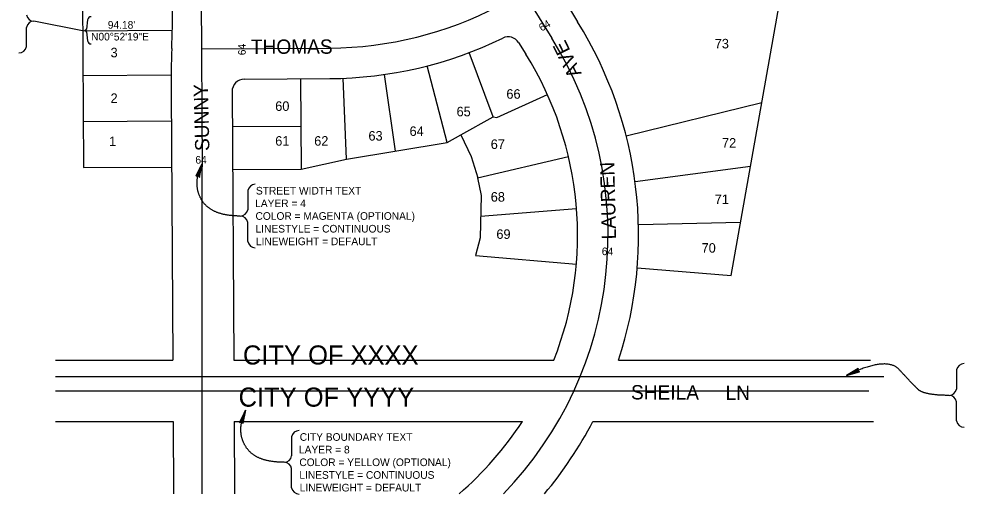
# Model space of a CAD drawing. Extents: x 6387474 to 6390971, y 1972046 to 1973920.
# Drawn here: x 6389012 to 6390004, y 1972046 to 1972544 of the extents above; entities that cross this region are included whole.
import ezdxf

# ---------------------------------------------------------------- set-up
doc = ezdxf.new("R2010")
doc.units = 0
for name, color, linetype in [('1', 7, 'Continuous'), ('2', 7, 'Continuous'), ('3', 7, 'Continuous'), ('4', 7, 'Continuous'), ('7', 7, 'Continuous'), ('8', 7, 'Continuous')]:
    doc.layers.add(name, color=color, linetype=linetype)

msp = doc.modelspace()

# ---------------------------------------------------------------- linework, layer by layer
at = {"layer": '1'}
for p, q in [((6389072.58, 1973552.73), (6389079.62, 1972388)), ((6389759.25, 1972274.95), (6389876.15, 1972929.69)), ((6389355.67, 1972396.74), (6389461.2, 1972414.36)), ((6389461.2, 1972414.36), (6389475.57, 1972422.29)), ((6389475.57, 1972422.29), (6389486.58, 1972399.76)), ((6389308.14, 1972386.48), (6389355.67, 1972396.74)), ((6389486.58, 1972399.76), (6389493.36, 1972377.14)), ((6389079.62, 1972388), (6389172.12, 1972388.56)), ((6389236.14, 1972386.04), (6389308.14, 1972386.48)), ((6389493.27, 1972377.12), (6389496.88, 1972358.76)), ((6389496.88, 1972358.76), (6389495.98, 1972314.39)), ((6389495.98, 1972314.39), (6389491.18, 1972295.81)), ((6389491.18, 1972295.81), (6389596.9, 1972286.77)), ((6389660.8, 1972282.98), (6389759.25, 1972274.95))]:
    msp.add_line(p, q, dxfattribs=at)
at = {"layer": '2'}
for p, q in [((6389202.67, 1972629.26), (6389204.12, 1972388.75)), ((6389540.91, 1972572.1), (6389571.1, 1972523.69)), ((6389203.37, 1972512.5), (6389337.91, 1972513.31)), ((6389204.12, 1972045.99), (6389204.12, 1972388.75)), ((6389050.21, 1972153.98), (6389903.78, 1972153.98))]:
    msp.add_line(p, q, dxfattribs=at)
for centre, radius, start, end in [((6389335.56, 1972901.3), 388, 270.34667, 18.92365), ((6389240.2, 1972317.28), 390, 315.92273, 31.95472)]:
    msp.add_arc(centre, radius, start, end, dxfattribs=at)
at = {"layer": '3'}
for p, q in [((6389078.76, 1972531.51), (6389172.94, 1972532.08)), ((6389509.78, 1972441.18), (6389484.28, 1972508.52)), ((6389461.2, 1972414.36), (6389440.49, 1972494.62)), ((6389079.04, 1972484.53), (6389171.69, 1972485.09)), ((6389407, 1972405.31), (6389395.46, 1972485.6)), ((6389307.56, 1972481.13), (6389308.14, 1972386.48)), ((6389355.67, 1972396.74), (6389352.05, 1972481.63)), ((6389513.51, 1972440.63), (6389566.5, 1972464.55)), ((6389791.56, 1972455.9), (6389649.3, 1972420.82)), ((6389079.33, 1972436.47), (6389171.83, 1972437.03)), ((6389475.57, 1972422.29), (6389509.78, 1972441.18)), ((6389509.78, 1972441.18), (6389513.51, 1972440.63)), ((6389235.87, 1972431.04), (6389307.86, 1972431.48)), ((6389493.27, 1972377.12), (6389588.59, 1972399.66)), ((6389779.64, 1972389.17), (6389658.5, 1972373.03)), ((6389496.44, 1972337.18), (6389597.12, 1972345)), ((6389769.17, 1972330.53), (6389662.07, 1972327.85))]:
    msp.add_line(p, q, dxfattribs=at)
at = {"layer": '4'}
for p, q in [((6389590.63, 1972552.84), (6389598.25, 1972540.63)), ((6389536.33, 1972518.97), (6389543.95, 1972506.75)), ((6389248.57, 1972480.77), (6389338.1, 1972481.31)), ((6389171.65, 1972467.3), (6389173.35, 1972185.98)), ((6389235.64, 1972467.69), (6389237.35, 1972185.98)), ((6389050.21, 1972185.98), (6389173.35, 1972185.98)), ((6389237.35, 1972185.98), (6389573.25, 1972185.98)), ((6389641.25, 1972185.98), (6389905.57, 1972185.98)), ((6389050.21, 1972121.98), (6389173.73, 1972121.98)), ((6389173.73, 1972121.98), (6389174.19, 1972045.99)), ((6389237.74, 1972121.98), (6389540.23, 1972121.98)), ((6389237.74, 1972121.98), (6389238.2, 1972045.99)), ((6389614.29, 1972121.98), (6389908.78, 1972121.98))]:
    msp.add_line(p, q, dxfattribs=at)
for centre, radius, start, end in [((6388172.12, 1972551.26), 1001, 357.80051, 0.34648), ((6389240.2, 1972317.28), 422, 341.87222, 31.95472), ((6389335.56, 1972901.3), 420, 270.34667, 295.98864), ((6389525.3, 1972512.09), 13, 31.95472, 115.98864), ((6390196.63, 1972473.51), 1025, 177.8005, 180.34667), ((6389240.2, 1972317.28), 358, 338.48409, 31.95472), ((6389248.64, 1972467.77), 13, 90.34667, 180.34667), ((6389240.2, 1972317.28), 358, 310.72876, 326.939), ((6389240.2, 1972317.28), 422, 319.99318, 332.43226)]:
    msp.add_arc(centre, radius, start, end, dxfattribs=at)
at = {"layer": '8'}
for p, q in [((6389084.02, 1972542.9), (6389082.81, 1972533.08)), ((6389019.82, 1972514.85), (6389019.82, 1972534.83)), ((6389078.76, 1972531.51), (6389027.71, 1972541.49)), ((6389082.81, 1972530.18), (6389084.02, 1972520.77)), ((6389203.73, 1972391.72), (6389197.52, 1972379.01)), ((6389201.33, 1972377.78), (6389203.73, 1972391.72)), ((6389252.13, 1972363.86), (6389252.13, 1972343.88)), ((6389252.13, 1972310.57), (6389252.13, 1972330.55)), ((6389892.6, 1972177.45), (6389880.46, 1972170.21)), ((6389995.91, 1972175.87), (6389995.91, 1972155.89)), ((6389050.21, 1972169.01), (6389919.45, 1972169.01)), ((6389880.46, 1972170.21), (6389894.15, 1972173.76)), ((6389995.91, 1972122.59), (6389995.91, 1972142.57)), ((6389249.7, 1972133.57), (6389243.49, 1972120.87)), ((6389247.3, 1972119.64), (6389249.7, 1972133.57)), ((6389298.1, 1972105.72), (6389298.1, 1972085.74)), ((6389298.1, 1972052.43), (6389298.1, 1972072.41))]:
    msp.add_line(p, q, dxfattribs=at)
for points in [[(6389197.52, 1972379.01), (6389198.03, 1972379.29), (6389203.73, 1972391.72)], [(6389198.03, 1972379.29), (6389198.59, 1972379.44), (6389203.73, 1972391.72)], [(6389198.59, 1972379.44), (6389199.16, 1972379.46), (6389203.73, 1972391.72)], [(6389199.16, 1972379.46), (6389199.73, 1972379.35), (6389203.73, 1972391.72)], [(6389199.73, 1972379.35), (6389200.26, 1972379.11), (6389203.73, 1972391.72)], [(6389203.73, 1972391.72), (6389200.26, 1972379.11), (6389200.71, 1972378.75)], [(6389203.73, 1972391.72), (6389200.71, 1972378.75), (6389201.08, 1972378.3)], [(6389203.73, 1972391.72), (6389201.08, 1972378.3), (6389201.33, 1972377.78)], [(6389880.46, 1972170.21), (6389892.37, 1972176.92), (6389892.6, 1972177.45)], [(6389880.46, 1972170.21), (6389892.27, 1972176.35), (6389892.37, 1972176.92)], [(6389880.46, 1972170.21), (6389892.29, 1972175.77), (6389892.27, 1972176.35)], [(6389892.45, 1972175.22), (6389892.29, 1972175.77), (6389880.46, 1972170.21)], [(6389892.74, 1972174.71), (6389892.45, 1972175.22), (6389880.46, 1972170.21)], [(6389893.13, 1972174.29), (6389892.74, 1972174.71), (6389880.46, 1972170.21)], [(6389893.61, 1972173.96), (6389893.13, 1972174.29), (6389880.46, 1972170.21)], [(6389894.15, 1972173.76), (6389893.61, 1972173.96), (6389880.46, 1972170.21)], [(6389243.49, 1972120.87), (6389244, 1972121.14), (6389249.7, 1972133.57)], [(6389244, 1972121.14), (6389244.55, 1972121.3), (6389249.7, 1972133.57)], [(6389244.55, 1972121.3), (6389245.13, 1972121.32), (6389249.7, 1972133.57)], [(6389245.13, 1972121.32), (6389245.7, 1972121.2), (6389249.7, 1972133.57)], [(6389245.7, 1972121.2), (6389246.23, 1972120.96), (6389249.7, 1972133.57)], [(6389249.7, 1972133.57), (6389246.23, 1972120.96), (6389246.68, 1972120.61)], [(6389249.7, 1972133.57), (6389246.68, 1972120.61), (6389247.04, 1972120.16)], [(6389249.7, 1972133.57), (6389247.04, 1972120.16), (6389247.3, 1972119.64)]]:
    msp.add_lwpolyline(points, close=True, dxfattribs=at)
for points in [[(6389198.97, 1972373.96), (6389199.02, 1972374.58), (6389199.08, 1972375.2), (6389199.14, 1972375.83), (6389199.22, 1972376.46), (6389199.31, 1972377.09), (6389199.4, 1972377.72), (6389199.51, 1972378.36), (6389199.62, 1972379), (6389199.75, 1972379.64), (6389199.89, 1972380.29), (6389200.03, 1972380.93), (6389200.19, 1972381.59), (6389200.36, 1972382.24), (6389200.53, 1972382.9), (6389200.72, 1972383.56), (6389200.91, 1972384.22), (6389201.12, 1972384.89), (6389201.34, 1972385.56), (6389201.56, 1972386.23), (6389201.8, 1972386.91), (6389202.04, 1972387.58), (6389202.3, 1972388.27), (6389202.57, 1972388.95), (6389202.84, 1972389.64), (6389203.13, 1972390.33), (6389203.43, 1972391.02), (6389203.73, 1972391.72)], [(6389244.24, 1972337.22), (6389243.31, 1972337.22), (6389242.38, 1972337.23), (6389241.47, 1972337.25), (6389240.56, 1972337.28), (6389239.67, 1972337.32), (6389238.78, 1972337.36), (6389237.9, 1972337.41), (6389237.03, 1972337.47), (6389236.18, 1972337.54), (6389235.33, 1972337.62), (6389234.49, 1972337.7), (6389233.66, 1972337.79), (6389232.84, 1972337.89), (6389232.04, 1972338), (6389231.24, 1972338.12), (6389230.45, 1972338.24), (6389229.67, 1972338.38), (6389228.9, 1972338.52), (6389228.14, 1972338.67), (6389227.39, 1972338.82), (6389226.64, 1972338.99), (6389225.91, 1972339.16), (6389225.19, 1972339.34), (6389224.48, 1972339.53), (6389223.78, 1972339.72), (6389223.09, 1972339.93), (6389222.4, 1972340.14), (6389221.73, 1972340.36), (6389221.07, 1972340.59), (6389220.41, 1972340.83), (6389219.77, 1972341.07), (6389219.13, 1972341.33), (6389218.51, 1972341.59), (6389217.9, 1972341.85), (6389217.29, 1972342.13), (6389216.69, 1972342.42), (6389216.11, 1972342.71), (6389215.53, 1972343.01), (6389214.97, 1972343.32), (6389214.41, 1972343.64), (6389213.86, 1972343.96), (6389213.33, 1972344.29), (6389212.8, 1972344.63), (6389212.28, 1972344.98), (6389211.77, 1972345.34), (6389211.28, 1972345.71), (6389210.79, 1972346.08), (6389210.31, 1972346.46), (6389209.84, 1972346.85), (6389209.38, 1972347.25), (6389208.93, 1972347.65), (6389208.49, 1972348.07), (6389208.06, 1972348.49), (6389207.64, 1972348.92), (6389207.23, 1972349.35), (6389206.83, 1972349.8), (6389206.43, 1972350.25), (6389206.05, 1972350.71), (6389205.68, 1972351.18), (6389205.32, 1972351.66), (6389204.97, 1972352.15), (6389204.62, 1972352.64), (6389204.29, 1972353.14), (6389203.97, 1972353.65), (6389203.65, 1972354.16), (6389203.35, 1972354.68), (6389203.06, 1972355.2), (6389202.77, 1972355.72), (6389202.5, 1972356.24), (6389202.23, 1972356.77), (6389201.98, 1972357.3), (6389201.74, 1972357.83), (6389201.5, 1972358.37), (6389201.28, 1972358.91), (6389201.07, 1972359.45), (6389200.86, 1972359.99), (6389200.67, 1972360.54), (6389200.49, 1972361.09), (6389200.31, 1972361.65), (6389200.15, 1972362.2), (6389199.99, 1972362.76), (6389199.85, 1972363.33), (6389199.72, 1972363.89), (6389199.59, 1972364.46), (6389199.48, 1972365.03), (6389199.38, 1972365.61), (6389199.28, 1972366.18), (6389199.2, 1972366.77), (6389199.13, 1972367.35), (6389199.06, 1972367.94), (6389199.01, 1972368.52), (6389198.96, 1972369.12), (6389198.93, 1972369.71), (6389198.91, 1972370.31), (6389198.89, 1972370.91), (6389198.89, 1972371.52), (6389198.9, 1972372.12), (6389198.91, 1972372.73), (6389198.94, 1972373.35), (6389198.97, 1972373.96)], [(6389938.55, 1972173.17), (6389938.08, 1972173.68), (6389937.61, 1972174.19), (6389937.13, 1972174.7), (6389936.65, 1972175.22), (6389936.16, 1972175.75), (6389935.67, 1972176.28), (6389935.16, 1972176.81), (6389934.63, 1972177.31), (6389934.09, 1972177.78), (6389933.52, 1972178.23), (6389932.93, 1972178.65), (6389932.32, 1972179.05), (6389931.69, 1972179.43), (6389931.05, 1972179.78), (6389930.37, 1972180.11), (6389929.68, 1972180.41), (6389928.97, 1972180.69), (6389928.24, 1972180.94), (6389927.49, 1972181.17), (6389926.71, 1972181.37), (6389925.92, 1972181.55), (6389925.1, 1972181.71), (6389924.27, 1972181.84), (6389923.41, 1972181.95), (6389922.54, 1972182.03), (6389921.64, 1972182.08), (6389920.72, 1972182.12), (6389919.78, 1972182.12), (6389918.82, 1972182.11), (6389917.84, 1972182.07), (6389916.84, 1972182), (6389915.82, 1972181.91), (6389914.78, 1972181.8), (6389913.72, 1972181.66), (6389912.63, 1972181.49), (6389911.53, 1972181.31), (6389910.41, 1972181.09), (6389909.26, 1972180.86), (6389908.1, 1972180.59), (6389906.91, 1972180.31), (6389905.7, 1972180), (6389904.48, 1972179.66), (6389903.23, 1972179.3), (6389901.96, 1972178.92), (6389900.67, 1972178.51), (6389899.36, 1972178.08), (6389898.03, 1972177.62), (6389896.68, 1972177.14), (6389895.31, 1972176.63), (6389893.92, 1972176.1), (6389892.5, 1972175.54), (6389891.07, 1972174.96), (6389889.61, 1972174.36), (6389888.14, 1972173.73), (6389886.64, 1972173.07), (6389885.13, 1972172.39), (6389883.59, 1972171.69), (6389882.03, 1972170.96), (6389880.46, 1972170.21)], [(6389988.02, 1972149.23), (6389987.05, 1972149.23), (6389986.08, 1972149.24), (6389985.13, 1972149.25), (6389984.19, 1972149.27), (6389983.27, 1972149.29), (6389982.36, 1972149.31), (6389981.47, 1972149.34), (6389980.59, 1972149.38), (6389979.72, 1972149.42), (6389978.87, 1972149.46), (6389978.03, 1972149.51), (6389977.2, 1972149.56), (6389976.39, 1972149.62), (6389975.59, 1972149.68), (6389974.81, 1972149.75), (6389974.04, 1972149.82), (6389973.28, 1972149.89), (6389972.54, 1972149.97), (6389971.81, 1972150.06), (6389971.1, 1972150.15), (6389970.4, 1972150.24), (6389969.71, 1972150.34), (6389969.04, 1972150.44), (6389968.38, 1972150.55), (6389967.74, 1972150.66), (6389967.11, 1972150.78), (6389966.49, 1972150.9), (6389965.89, 1972151.03), (6389965.3, 1972151.16), (6389964.72, 1972151.29), (6389964.16, 1972151.43), (6389963.62, 1972151.58), (6389963.08, 1972151.72), (6389962.56, 1972151.88), (6389962.06, 1972152.04), (6389961.57, 1972152.2), (6389961.09, 1972152.37), (6389960.63, 1972152.54), (6389960.18, 1972152.71), (6389959.74, 1972152.9), (6389959.32, 1972153.08), (6389958.91, 1972153.27), (6389958.52, 1972153.47), (6389958.14, 1972153.67), (6389957.77, 1972153.87), (6389957.42, 1972154.08), (6389957.08, 1972154.29), (6389956.76, 1972154.51), (6389956.45, 1972154.73), (6389956.15, 1972154.96), (6389955.87, 1972155.19), (6389955.6, 1972155.42), (6389955.35, 1972155.67), (6389955.1, 1972155.91), (6389954.84, 1972156.16), (6389954.58, 1972156.42), (6389954.32, 1972156.68), (6389954.05, 1972156.95), (6389953.78, 1972157.22), (6389953.5, 1972157.5), (6389953.22, 1972157.78), (6389952.93, 1972158.07), (6389952.64, 1972158.37), (6389952.34, 1972158.67), (6389952.04, 1972158.98), (6389951.73, 1972159.29), (6389951.42, 1972159.61), (6389951.11, 1972159.93), (6389950.79, 1972160.26), (6389950.46, 1972160.59), (6389950.14, 1972160.93), (6389949.8, 1972161.28), (6389949.46, 1972161.63), (6389949.12, 1972161.98), (6389948.77, 1972162.34), (6389948.42, 1972162.71), (6389948.06, 1972163.08), (6389947.7, 1972163.46), (6389947.33, 1972163.84), (6389946.96, 1972164.23), (6389946.59, 1972164.63), (6389946.2, 1972165.03), (6389945.82, 1972165.43), (6389945.43, 1972165.84), (6389945.03, 1972166.26), (6389944.63, 1972166.68), (6389944.23, 1972167.11), (6389943.82, 1972167.54), (6389943.41, 1972167.98), (6389942.99, 1972168.43), (6389942.57, 1972168.88), (6389942.14, 1972169.33), (6389941.71, 1972169.79), (6389941.27, 1972170.26), (6389940.83, 1972170.73), (6389940.38, 1972171.21), (6389939.93, 1972171.69), (6389939.48, 1972172.18), (6389939.02, 1972172.67), (6389938.55, 1972173.17)], [(6389244.94, 1972115.82), (6389244.99, 1972116.44), (6389245.05, 1972117.06), (6389245.11, 1972117.69), (6389245.19, 1972118.31), (6389245.27, 1972118.95), (6389245.37, 1972119.58), (6389245.48, 1972120.22), (6389245.59, 1972120.86), (6389245.72, 1972121.5), (6389245.86, 1972122.14), (6389246, 1972122.79), (6389246.16, 1972123.44), (6389246.32, 1972124.1), (6389246.5, 1972124.76), (6389246.69, 1972125.42), (6389246.88, 1972126.08), (6389247.09, 1972126.75), (6389247.3, 1972127.42), (6389247.53, 1972128.09), (6389247.77, 1972128.76), (6389248.01, 1972129.44), (6389248.27, 1972130.12), (6389248.54, 1972130.81), (6389248.81, 1972131.49), (6389249.1, 1972132.18), (6389249.39, 1972132.88), (6389249.7, 1972133.57)], [(6389290.21, 1972079.08), (6389289.28, 1972079.08), (6389288.35, 1972079.09), (6389287.44, 1972079.11), (6389286.53, 1972079.14), (6389285.63, 1972079.18), (6389284.75, 1972079.22), (6389283.87, 1972079.27), (6389283, 1972079.33), (6389282.15, 1972079.4), (6389281.3, 1972079.48), (6389280.46, 1972079.56), (6389279.63, 1972079.65), (6389278.81, 1972079.75), (6389278, 1972079.86), (6389277.2, 1972079.98), (6389276.42, 1972080.1), (6389275.64, 1972080.23), (6389274.87, 1972080.37), (6389274.11, 1972080.52), (6389273.35, 1972080.68), (6389272.61, 1972080.84), (6389271.88, 1972081.02), (6389271.16, 1972081.2), (6389270.45, 1972081.39), (6389269.75, 1972081.58), (6389269.05, 1972081.79), (6389268.37, 1972082), (6389267.7, 1972082.22), (6389267.03, 1972082.45), (6389266.38, 1972082.69), (6389265.74, 1972082.93), (6389265.1, 1972083.18), (6389264.48, 1972083.44), (6389263.86, 1972083.71), (6389263.26, 1972083.99), (6389262.66, 1972084.27), (6389262.08, 1972084.57), (6389261.5, 1972084.87), (6389260.94, 1972085.18), (6389260.38, 1972085.49), (6389259.83, 1972085.82), (6389259.3, 1972086.15), (6389258.77, 1972086.49), (6389258.25, 1972086.84), (6389257.74, 1972087.2), (6389257.24, 1972087.56), (6389256.76, 1972087.94), (6389256.28, 1972088.32), (6389255.81, 1972088.71), (6389255.35, 1972089.1), (6389254.9, 1972089.51), (6389254.46, 1972089.92), (6389254.03, 1972090.34), (6389253.61, 1972090.77), (6389253.2, 1972091.21), (6389252.79, 1972091.66), (6389252.4, 1972092.11), (6389252.02, 1972092.57), (6389251.65, 1972093.04), (6389251.29, 1972093.52), (6389250.93, 1972094), (6389250.59, 1972094.5), (6389250.26, 1972095), (6389249.93, 1972095.51), (6389249.62, 1972096.02), (6389249.32, 1972096.54), (6389249.02, 1972097.05), (6389248.74, 1972097.57), (6389248.47, 1972098.1), (6389248.2, 1972098.63), (6389247.95, 1972099.16), (6389247.71, 1972099.69), (6389247.47, 1972100.23), (6389247.25, 1972100.77), (6389247.03, 1972101.31), (6389246.83, 1972101.85), (6389246.64, 1972102.4), (6389246.45, 1972102.95), (6389246.28, 1972103.51), (6389246.12, 1972104.06), (6389245.96, 1972104.62), (6389245.82, 1972105.18), (6389245.69, 1972105.75), (6389245.56, 1972106.32), (6389245.45, 1972106.89), (6389245.34, 1972107.47), (6389245.25, 1972108.04), (6389245.17, 1972108.62), (6389245.09, 1972109.21), (6389245.03, 1972109.79), (6389244.98, 1972110.38), (6389244.93, 1972110.98), (6389244.9, 1972111.57), (6389244.88, 1972112.17), (6389244.86, 1972112.77), (6389244.86, 1972113.37), (6389244.86, 1972113.98), (6389244.88, 1972114.59), (6389244.91, 1972115.2), (6389244.94, 1972115.82)]]:
    msp.add_lwpolyline(points, dxfattribs=at)
for centre, radius, start, end in [((6389027.71, 1972549.49), 8, 189.61952, 270), ((6389087.67, 1972542.45), 3.68, 86.25389, 172.99909), ((6389027.71, 1972533.49), 8, 90, 170.38048), ((6389081.17, 1972533.28), 1.66, 270, 352.99909), ((6389081.17, 1972529.97), 1.66, 7.3237, 90), ((6389011.93, 1972516.18), 8, 270, 350.38048), ((6389087.67, 1972521.23), 3.68, 187.3237, 273.74611), ((6389198.96, 1972376.97), 2.5, 18.95091, 125.21111), ((6389260.02, 1972362.52), 8, 90, 170.38048), ((6389244.24, 1972345.22), 8, 270, 350.38048), ((6389244.24, 1972329.22), 8, 9.61952, 90), ((6389260.02, 1972311.91), 8, 189.61952, 270), ((6389894.76, 1972176.18), 2.5, 149.5258, 255.78601), ((6390003.8, 1972174.54), 8, 90, 170.38048), ((6389988.02, 1972157.23), 8, 270, 350.38048), ((6389988.02, 1972141.23), 8, 9.61952, 90), ((6389244.93, 1972118.83), 2.5, 18.95091, 125.21111), ((6390003.8, 1972123.92), 8, 189.61952, 270), ((6389305.99, 1972104.38), 8, 90, 170.38048), ((6389290.21, 1972087.07), 8, 270, 350.38048), ((6389290.21, 1972071.07), 8, 9.61952, 90), ((6389305.99, 1972053.77), 8, 189.61952, 270)]:
    msp.add_arc(centre, radius, start, end, dxfattribs=at)

# ---------------------------------------------------------------- texts
at = {"layer": '2'}
for s, rotation, p in [('THOMAS ', 0.06391, (6389255.37, 1972507.21)), ('AVE', 116.20376, (6389602.77, 1972486.63)), ('SUNNY ', 91.44887, (6389211.93, 1972405.52)), ('LAUREN', 91.44887, (6389638.7, 1972312.82)), ('SHEILA     LN', 359.71156, (6389654.23, 1972144.99))]:
    msp.add_text(s, height=15, rotation=rotation, dxfattribs=at).set_placement(p)
at = {"layer": '4'}
for rotation, p in [(31.52155, (6389560.61, 1972530.37)), (90.90209, (6389250.02, 1972505.83)), (1.5787, (6389197.24, 1972392.03)), (358.93218, (6389623.52, 1972296.27))]:
    msp.add_text('64', height=8, rotation=rotation, dxfattribs=at).set_placement(p)
at = {"layer": '7'}
for s, p in [('73', (6389742.14, 1972512.91)), ('3', (6389108.11, 1972503.57)), ('2', (6389108.11, 1972455.71)), ('66', (6389523.5, 1972460.15)), ('60', (6389280.91, 1972447.43)), ('65', (6389471.2, 1972441.73)), ('65', (6389471.2, 1972441.73)), ('63', (6389378.74, 1972416.28)), ('64', (6389421.88, 1972421.17)), ('1', (6389106.58, 1972410.54)), ('61', (6389280.91, 1972410.94)), ('61', (6389280.91, 1972410.94)), ('62', (6389321.82, 1972410.94)), ('67', (6389507.07, 1972407.53)), ('72', (6389749.74, 1972408.89)), ('68', (6389507.07, 1972352.29)), ('71', (6389742.14, 1972349.76)), ('69', (6389512.98, 1972313.26)), ('70', (6389728.34, 1972298.79))]:
    msp.add_text(s, height=10, dxfattribs=at).set_placement(p)
at = {"layer": '8'}
for s, height, p in [("94.18'", 8, (6389105.21, 1972533.56)), ('N00°52\'19"E', 8, (6389087.67, 1972521.24)), ('STREET WIDTH TEXT', 8, (6389260.66, 1972359.76)), ('LAYER = 4', 8, (6389259.85, 1972346.51)), ('COLOR = MAGENTA (OPTIONAL)', 8, (6389260.24, 1972333.25)), ('LINESTYLE = CONTINUOUS', 8, (6389260.24, 1972319.93)), ('LINEWEIGHT = DEFAULT', 8, (6389260.64, 1972306.67)), ('CITY OF XXXX', 20, (6389247.07, 1972181.59)), ('CITY OF YYYY', 20, (6389242.5, 1972137.41)), ('CITY BOUNDARY TEXT', 8, (6389306.63, 1972101.61)), ('LAYER = 8', 8, (6389305.82, 1972088.37)), ('COLOR = YELLOW (OPTIONAL)', 8, (6389306.21, 1972075.11)), ('LINESTYLE = CONTINUOUS', 8, (6389306.21, 1972061.79)), ('LINEWEIGHT = DEFAULT', 8, (6389306.6, 1972048.53))]:
    msp.add_text(s, height=height, dxfattribs=at).set_placement(p)

doc.saveas('drawing.dxf')
